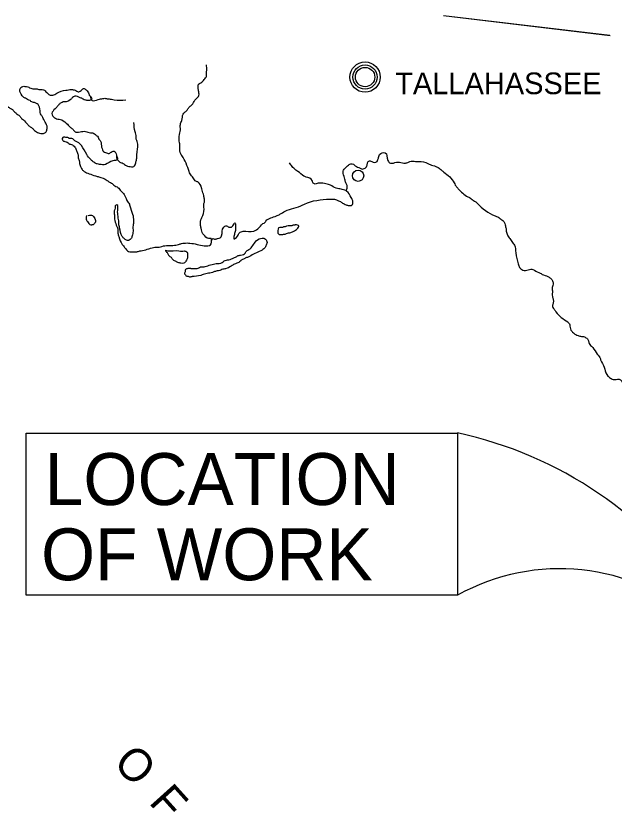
# Model space of a CAD drawing. Extents: x 492225 to 553725, y 1303773 to 1347273.
# Drawn here: x 537404 to 540852, y 1339055 to 1343645 of the extents above; entities that cross this region are included whole.
import ezdxf

# ---------------------------------------------------------------- set-up
doc = ezdxf.new("R2010")
doc.units = 0
for name, color, linetype in [('Level 1', 7, 'Continuous'), ('Level 20', 7, 'Continuous'), ('Level 62', 7, 'Continuous'), ('Level 63', 7, 'Continuous')]:
    doc.layers.add(name, color=color, linetype=linetype)

msp = doc.modelspace()

# ---------------------------------------------------------------- linework, layer by layer
at = {"layer": 'Level 1'}
msp.add_lwpolyline([(539950.039, 1340305.02), (537462.341, 1340305.02), (537462.341, 1341240.247), (539950.039, 1341240.247)], close=True, dxfattribs=at)
for centre, radius, start, end in [((539463.2113, 1338980.6391), 2311.473, 33.7540933, 77.84251), ((540538.5032, 1339245.9527), 1211.5972, 48.8625679, 119.0596401)]:
    msp.add_arc(centre, radius, start, end, dxfattribs=at)
at = {"layer": 'Level 62'}
for radius in [69.8771, 55.9017]:
    msp.add_circle((539416.527, 1343292.5055), radius, dxfattribs=at)
at = {"layer": 'Level 63'}
for p, q in [((540828.4745, 1343531.248), (539868.327, 1343644.788)), ((539336.562, 1342597.5055), (539335.312, 1342598.7555))]:
    msp.add_line(p, q, dxfattribs=at)
for points in [[(540349.062, 1343587.5055), (539867.812, 1343645.0055)], [(540830.312, 1343530.0055), (540349.062, 1343587.5055)]]:
    msp.add_lwpolyline(points, dxfattribs=at)
for centre, radius in [((539416.527, 1343292.5055), 87.3464), ((539376.527, 1342723.7555), 32.5)]:
    msp.add_circle(centre, radius, dxfattribs=at)
for points in [[(536941.562, 1343353.7555), (536991.562, 1343343.7555), (537006.562, 1343336.2555), (537024.062, 1343331.2555), (537042.812, 1343323.7555), (537052.812, 1343321.2555), (537070.312, 1343313.7555), (537082.812, 1343306.2555), (537100.312, 1343293.7555), (537107.812, 1343291.2555), (537122.812, 1343281.2555), (537132.812, 1343276.2555), (537150.312, 1343263.7555), (537171.562, 1343251.2555), (537181.562, 1343243.7555), (537186.562, 1343238.7555), (537201.562, 1343231.2555), (537214.062, 1343221.2555), (537229.062, 1343213.7555), (537249.062, 1343198.7555), (537261.562, 1343191.2555), (537269.062, 1343183.7555), (537300.312, 1343166.2555), (537360.312, 1343118.7555), (537377.812, 1343108.7555), (537387.812, 1343101.2555), (537392.812, 1343093.7555), (537402.812, 1343086.2555), (537407.812, 1343081.2555), (537424.062, 1343068.7555), (537436.562, 1343053.7555), (537446.562, 1343046.2555), (537471.562, 1343018.7555), (537486.562, 1343006.2555), (537494.062, 1343001.2555), (537506.562, 1342988.7555), (537527.812, 1342973.7555), (537540.312, 1342968.7555), (537555.312, 1342966.2555), (537570.312, 1342971.2555), (537577.812, 1342976.2555), (537582.812, 1342996.2555), (537582.812, 1343008.7555), (537576.562, 1343026.2555), (537569.062, 1343040.0055), (537564.062, 1343047.5055), (537559.062, 1343060.0055), (537549.062, 1343075.0055), (537544.062, 1343087.5055), (537536.562, 1343127.5055), (537510.312, 1343145.0055), (537490.312, 1343152.5055), (537485.312, 1343157.5055), (537470.312, 1343162.5055), (537460.312, 1343170.0055), (537452.812, 1343172.5055), (537440.312, 1343185.0055), (537425.312, 1343217.5055), (537432.812, 1343232.5055), (537442.812, 1343238.7555), (537455.312, 1343238.7555), (537472.812, 1343236.2555), (537482.812, 1343231.2555), (537507.812, 1343223.7555), (537525.312, 1343223.7555), (537535.312, 1343221.2555), (537555.312, 1343221.2555), (537567.812, 1343216.2555), (537585.312, 1343198.7555), (537601.562, 1343188.7555), (537616.562, 1343188.7555), (537639.062, 1343198.7555), (537691.562, 1343217.5055), (537699.062, 1343217.5055), (537714.062, 1343220.0055), (537729.062, 1343220.0055), (537749.062, 1343215.0055), (537761.562, 1343207.5055), (537779.062, 1343215.0055), (537794.062, 1343226.2555), (537809.062, 1343218.7555), (537824.062, 1343195.0055), (537826.562, 1343187.5055), (537831.562, 1343182.5055)], [(538531.562, 1342348.7555), (538529.062, 1342361.2555), (538514.062, 1342361.2555), (538486.562, 1342383.7555), (538481.562, 1342388.7555), (538471.562, 1342421.2555), (538467.812, 1342441.2555), (538472.812, 1342477.5055), (538480.312, 1342495.0055), (538487.812, 1342542.5055), (538487.812, 1342563.7555), (538490.312, 1342571.2555), (538490.312, 1342588.7555), (538486.562, 1342608.7555), (538476.562, 1342641.2555), (538474.062, 1342653.7555), (538451.562, 1342687.5055), (538436.562, 1342695.0055), (538429.062, 1342705.0055), (538421.562, 1342717.5055), (538416.562, 1342722.5055), (538407.812, 1342735.0055), (538402.812, 1342747.5055), (538360.312, 1342840.0055), (538354.062, 1342850.0055), (538349.062, 1342886.2555), (538349.062, 1342901.2555), (538346.562, 1342913.7555), (538346.562, 1342961.2555), (538351.562, 1342997.5055), (538350.312, 1343007.5055), (538355.312, 1343030.0055), (538360.312, 1343042.5055), (538367.812, 1343078.7555), (538375.312, 1343088.7555), (538390.312, 1343101.2555), (538395.312, 1343108.7555), (538407.812, 1343123.7555), (538422.812, 1343138.7555), (538440.312, 1343165.0055), (538455.312, 1343180.0055), (538457.812, 1343207.5055), (538455.312, 1343217.5055), (538454.062, 1343235.0055), (538456.562, 1343251.2555), (538469.062, 1343258.7555), (538489.062, 1343278.7555), (538501.562, 1343296.2555), (538501.562, 1343313.7555), (538504.062, 1343332.5055), (538504.062, 1343347.5055), (538501.562, 1343362.5055)], [(537831.562, 1343182.5055), (537840.312, 1343162.5055), (537822.812, 1343157.5055), (537804.062, 1343160.0055), (537791.562, 1343165.0055), (537784.062, 1343170.0055), (537774.062, 1343172.5055), (537759.062, 1343180.0055), (537744.062, 1343182.5055), (537726.562, 1343170.0055), (537721.562, 1343165.0055), (537709.062, 1343156.2555), (537699.062, 1343151.2555), (537676.562, 1343148.7555), (537664.062, 1343143.7555), (537651.562, 1343133.7555), (537639.062, 1343118.7555), (537629.062, 1343108.7555), (537611.562, 1343082.5055), (537616.562, 1343067.5055), (537637.812, 1343052.5055), (537667.812, 1343045.0055), (537700.312, 1343020.0055), (537717.812, 1343002.5055), (537732.812, 1342990.0055), (537745.312, 1342977.5055), (537765.312, 1342975.0055), (537796.562, 1342980.0055), (537811.562, 1342977.5055), (537826.562, 1342972.5055), (537841.562, 1342971.2555), (537861.562, 1342961.2555), (537866.562, 1342956.2555), (537874.062, 1342951.2555), (537879.062, 1342940.0055), (537891.562, 1342922.5055), (537897.812, 1342887.5055), (537902.812, 1342872.5055), (537907.812, 1342862.5055), (537920.312, 1342857.5055), (537940.312, 1342852.5055), (537957.812, 1342862.5055), (537970.312, 1342865.0055), (537982.812, 1342842.5055)], [(537831.562, 1343182.5055), (537842.812, 1343157.5055), (537877.812, 1343162.5055), (537905.312, 1343168.7555), (537925.312, 1343168.7555), (537932.812, 1343166.2555), (537940.312, 1343166.2555), (537970.312, 1343161.2555), (538037.812, 1343161.2555)], [(537982.812, 1342842.5055), (537987.812, 1342817.5055), (538002.812, 1342802.5055), (538021.562, 1342795.0055), (538039.062, 1342782.5055), (538054.062, 1342777.5055), (538069.062, 1342775.0055), (538084.062, 1342777.5055), (538094.062, 1342797.5055), (538099.062, 1342818.7555), (538101.562, 1342841.2555), (538101.562, 1342851.2555), (538102.812, 1342861.2555), (538102.812, 1342920.0055), (538097.812, 1342935.0055), (538097.812, 1342950.0055), (538095.312, 1342962.5055), (538090.312, 1342977.5055), (538084.062, 1343030.0055)], [(537982.812, 1342842.5055), (537987.812, 1342815.0055), (537962.812, 1342810.0055), (537920.312, 1342788.7555), (537885.312, 1342788.7555), (537872.812, 1342791.2555), (537857.812, 1342798.7555), (537840.312, 1342811.2555), (537835.312, 1342816.2555), (537811.562, 1342846.2555), (537781.562, 1342897.5055), (537766.562, 1342912.5055), (537759.062, 1342917.5055), (537744.062, 1342925.0055), (537726.562, 1342937.5055), (537710.312, 1342938.7555), (537702.812, 1342943.7555), (537695.312, 1342943.7555), (537677.812, 1342946.2555), (537670.312, 1342938.7555), (537677.812, 1342923.7555), (537686.562, 1342921.2555), (537699.062, 1342916.2555), (537709.062, 1342908.7555), (537729.062, 1342901.2555), (537746.562, 1342883.7555), (537751.562, 1342873.7555), (537759.062, 1342853.7555), (537761.562, 1342843.7555), (537764.062, 1342821.2555), (537767.812, 1342811.2555), (537770.312, 1342793.7555), (537777.812, 1342772.5055), (537785.312, 1342760.0055), (537797.812, 1342747.5055), (537825.312, 1342735.0055), (537862.812, 1342722.5055), (537881.562, 1342717.5055), (537929.062, 1342696.2555), (537944.062, 1342686.2555), (537954.062, 1342681.2555), (537974.062, 1342666.2555), (537986.562, 1342658.7555), (537996.562, 1342651.2555), (538004.062, 1342641.2555), (538020.312, 1342625.0055), (538027.812, 1342615.0055), (538050.312, 1342570.0055), (538057.812, 1342560.0055), (538060.312, 1342550.0055), (538076.562, 1342502.5055), (538081.562, 1342463.7555), (538081.562, 1342448.7555), (538079.062, 1342436.2555), (538079.062, 1342403.7555), (538074.062, 1342376.2555), (538066.562, 1342360.0055), (538046.562, 1342350.0055), (538029.062, 1342360.0055), (538016.562, 1342372.5055), (538001.562, 1342423.7555), (537996.562, 1342446.2555), (537996.562, 1342463.7555), (537992.812, 1342478.7555), (537992.812, 1342491.2555), (537990.312, 1342506.2555), (537990.312, 1342523.7555), (537985.312, 1342555.0055), (537977.812, 1342552.5055), (537975.312, 1342536.2555), (537970.312, 1342521.2555), (537970.312, 1342503.7555), (537972.812, 1342483.7555), (537972.812, 1342473.7555), (537991.562, 1342405.0055), (537991.562, 1342392.5055), (537996.562, 1342372.5055), (538016.562, 1342327.5055), (538030.312, 1342310.0055), (538052.812, 1342287.5055), (538070.312, 1342285.0055), (538100.312, 1342285.0055), (538117.812, 1342290.0055), (538132.812, 1342292.5055), (538170.312, 1342302.5055), (538180.312, 1342306.2555), (538212.812, 1342311.2555), (538230.312, 1342311.2555), (538245.312, 1342316.2555), (538280.312, 1342321.2555), (538309.062, 1342321.2555)], [(539307.812, 1342638.7555), (539312.812, 1342652.5055), (539312.812, 1342667.5055), (539305.312, 1342682.5055), (539300.312, 1342703.7555), (539290.312, 1342736.2555), (539290.312, 1342751.2555), (539302.812, 1342768.7555), (539307.812, 1342773.7555), (539325.312, 1342787.5055), (539342.812, 1342792.5055), (539355.312, 1342785.0055), (539360.312, 1342780.0055), (539387.812, 1342767.5055), (539395.312, 1342762.5055), (539405.312, 1342762.5055), (539417.812, 1342767.5055), (539427.812, 1342785.0055), (539432.812, 1342802.5055), (539437.812, 1342807.5055), (539445.312, 1342810.0055), (539455.312, 1342805.0055), (539470.312, 1342800.0055), (539485.312, 1342806.2555), (539490.312, 1342816.2555), (539495.312, 1342833.7555), (539500.312, 1342846.2555), (539532.812, 1342856.2555), (539547.812, 1342811.2555), (539562.812, 1342796.2555), (539597.812, 1342801.2555), (539614.062, 1342801.2555), (539649.062, 1342796.2555), (539666.562, 1342802.5055), (539699.062, 1342807.5055), (539716.562, 1342805.0055), (539726.562, 1342805.0055), (539779.062, 1342795.0055), (539791.562, 1342787.5055), (539824.062, 1342777.5055), (539842.812, 1342767.5055), (539852.812, 1342760.0055), (539857.812, 1342755.0055), (539870.312, 1342745.0055), (539930.312, 1342682.5055), (539936.562, 1342670.0055), (539941.562, 1342662.5055), (539954.062, 1342647.5055), (540009.062, 1342602.5055), (540019.062, 1342597.5055), (540037.812, 1342582.5055), (540055.312, 1342572.5055), (540062.812, 1342565.0055), (540166.562, 1342492.5055), (540194.062, 1342477.5055), (540199.062, 1342472.5055), (540211.562, 1342465.0055), (540219.062, 1342455.0055), (540224.062, 1342440.0055), (540229.062, 1342418.7555), (540231.562, 1342398.7555), (540240.312, 1342376.2555), (540255.312, 1342356.2555), (540262.812, 1342343.7555), (540277.812, 1342323.7555), (540285.312, 1342278.7555), (540299.062, 1342215.0055), (540306.562, 1342195.0055), (540326.562, 1342180.0055), (540341.562, 1342177.5055), (540371.562, 1342185.0055), (540384.062, 1342182.5055), (540417.812, 1342165.0055), (540425.312, 1342162.5055), (540437.812, 1342155.0055), (540470.312, 1342142.5055), (540485.312, 1342132.5055), (540497.812, 1342117.5055), (540500.312, 1342097.5055), (540495.312, 1342072.5055), (540496.562, 1342060.0055), (540496.562, 1342027.5055), (540499.062, 1342018.7555), (540499.062, 1341981.2555), (540496.562, 1341973.7555), (540506.562, 1341953.7555), (540516.562, 1341938.7555), (540547.812, 1341906.2555), (540585.312, 1341881.2555)], [(539336.562, 1342597.5055), (539310.312, 1342635.0055), (539300.312, 1342640.0055), (539285.312, 1342645.0055), (539257.812, 1342650.0055), (539225.312, 1342665.0055), (539217.812, 1342670.0055), (539205.312, 1342672.5055), (539190.312, 1342677.5055), (539172.812, 1342680.0055), (539145.312, 1342680.0055), (539124.062, 1342676.2555), (539114.062, 1342688.7555), (539111.562, 1342696.2555), (539076.562, 1342716.2555), (539064.062, 1342721.2555), (539029.062, 1342748.7555), (539016.562, 1342756.2555), (539005.312, 1342766.2555), (538995.312, 1342777.5055), (538980.312, 1342797.5055)], [(538531.562, 1342348.7555), (538539.062, 1342361.2555), (538549.062, 1342358.7555), (538566.562, 1342361.2555), (538581.562, 1342366.2555), (538589.062, 1342377.5055), (538601.562, 1342427.5055), (538614.062, 1342435.0055), (538631.562, 1342427.5055), (538646.562, 1342427.5055), (538661.562, 1342446.2555), (538666.562, 1342451.2555), (538669.062, 1342433.7555), (538669.062, 1342407.5055), (538662.812, 1342385.0055), (538660.312, 1342372.5055), (538660.312, 1342360.0055), (538680.312, 1342375.0055), (538692.812, 1342395.0055), (538712.812, 1342403.7555), (538775.312, 1342403.7555), (538790.312, 1342411.2555), (538820.312, 1342441.2555), (538827.812, 1342447.5055), (538840.312, 1342455.0055), (538845.312, 1342462.5055), (538872.812, 1342480.0055), (538905.312, 1342492.5055), (538925.312, 1342501.2555), (538955.312, 1342518.7555), (539057.812, 1342555.0055), (539067.812, 1342560.0055), (539212.812, 1342588.7555), (539232.812, 1342588.7555), (539259.062, 1342581.2555), (539279.062, 1342571.2555), (539286.562, 1342566.2555), (539306.562, 1342556.2555), (539324.062, 1342551.2555), (539341.562, 1342555.0055), (539346.562, 1342572.5055), (539336.562, 1342597.5055)], [(537812.812, 1342493.7555), (537809.062, 1342487.5055), (537807.812, 1342480.0055), (537810.312, 1342467.5055), (537816.562, 1342460.0055), (537824.062, 1342447.5055), (537830.312, 1342442.5055), (537841.562, 1342441.2555)], [(537820.312, 1342493.7555), (537845.312, 1342493.7555), (537850.312, 1342488.7555), (537857.812, 1342476.2555), (537861.562, 1342456.2555), (537856.562, 1342448.7555), (537849.062, 1342441.2555), (537841.562, 1342441.2555)], [(538916.562, 1342425.0055), (538914.062, 1342407.5055), (538914.062, 1342392.5055), (538921.562, 1342385.0055), (538936.562, 1342385.0055), (538956.562, 1342387.5055), (538969.062, 1342392.5055), (538982.812, 1342395.0055), (539002.812, 1342402.5055), (539015.312, 1342410.0055), (539032.812, 1342426.2555), (539034.062, 1342433.7555), (539014.062, 1342441.2555)], [(538916.562, 1342423.7555), (538926.562, 1342426.2555), (538935.312, 1342426.2555), (538941.562, 1342427.5055), (538949.062, 1342430.0055), (538957.812, 1342431.2555), (538974.062, 1342436.2555), (538981.562, 1342436.2555), (538987.812, 1342437.5055), (538996.562, 1342437.5055), (539002.812, 1342440.0055), (539014.062, 1342441.2555)], [(538309.062, 1342321.2555), (538341.562, 1342327.5055), (538359.062, 1342332.5055), (538374.062, 1342335.0055), (538406.562, 1342335.0055), (538489.062, 1342320.0055), (538501.562, 1342318.7555), (538519.062, 1342321.2555), (538529.062, 1342331.2555), (538531.562, 1342348.7555)], [(538411.562, 1342188.7555), (538441.562, 1342188.7555), (538454.062, 1342191.2555), (538471.562, 1342198.7555), (538489.062, 1342198.7555), (538501.562, 1342201.2555), (538534.062, 1342212.5055), (538566.562, 1342217.5055), (538599.062, 1342227.5055), (538604.062, 1342232.5055), (538631.562, 1342238.7555), (538646.562, 1342243.7555), (538656.562, 1342248.7555), (538664.062, 1342251.2555), (538681.562, 1342261.2555), (538699.062, 1342266.2555), (538726.562, 1342278.7555), (538729.062, 1342285.0055), (538746.562, 1342297.5055), (538789.062, 1342347.5055), (538824.062, 1342363.7555), (538841.562, 1342358.7555), (538851.562, 1342338.7555), (538849.062, 1342328.7555), (538840.312, 1342310.0055), (538822.812, 1342295.0055), (538757.812, 1342262.5055), (538742.812, 1342253.7555), (538725.312, 1342248.7555), (538720.312, 1342243.7555), (538710.312, 1342241.2555), (538697.812, 1342231.2555), (538677.812, 1342218.7555), (538662.812, 1342213.7555), (538645.312, 1342202.5055), (538612.812, 1342187.5055), (538591.562, 1342182.5055), (538579.062, 1342177.5055), (538564.062, 1342175.0055), (538544.062, 1342168.7555), (538514.062, 1342161.2555), (538499.062, 1342158.7555), (538469.062, 1342148.7555), (538419.062, 1342142.5055)], [(538265.312, 1342293.7555), (538277.812, 1342291.2555), (538342.812, 1342291.2555), (538360.312, 1342288.7555), (538372.812, 1342290.0055), (538390.312, 1342282.5055), (538392.812, 1342258.7555), (538390.312, 1342243.7555), (538382.812, 1342231.2555), (538371.562, 1342218.7555), (538355.312, 1342218.7555), (538337.812, 1342223.7555), (538322.812, 1342231.2555), (538307.812, 1342241.2555), (538302.812, 1342248.7555), (538290.312, 1342258.7555)], [(538265.312, 1342293.7555), (538269.062, 1342286.2555), (538275.312, 1342280.0055), (538282.812, 1342265.0055), (538290.312, 1342258.7555)], [(538411.562, 1342188.7555), (538395.312, 1342188.7555), (538387.812, 1342186.2555), (538381.562, 1342182.5055), (538379.062, 1342175.0055), (538377.812, 1342165.0055), (538375.312, 1342157.5055), (538381.562, 1342152.5055), (538384.062, 1342146.2555), (538394.062, 1342145.0055), (538400.312, 1342142.5055), (538419.062, 1342142.5055)], [(540585.312, 1341881.2555), (540590.312, 1341873.7555), (540595.312, 1341868.7555), (540597.812, 1341856.2555), (540607.812, 1341827.5055), (540612.812, 1341822.5055), (540631.562, 1341807.5055), (540644.062, 1341802.5055), (540664.062, 1341797.5055), (540676.562, 1341796.2555), (540694.062, 1341786.2555), (540701.562, 1341778.7555), (540706.562, 1341762.5055), (540721.562, 1341740.0055), (540729.062, 1341732.5055), (540755.312, 1341695.0055), (540772.812, 1341667.5055), (540775.312, 1341657.5055), (540780.312, 1341650.0055), (540816.562, 1341568.7555), (540821.562, 1341563.7555), (540841.562, 1341551.2555), (540854.062, 1341548.7555), (540889.062, 1341547.5055), (540901.562, 1341526.2555), (540906.562, 1341508.7555), (540912.812, 1341498.7555), (540917.812, 1341473.7555), (540932.812, 1341433.7555), (540940.312, 1341421.2555), (540952.812, 1341406.2555), (540965.312, 1341401.2555), (540980.312, 1341398.7555), (541012.812, 1341413.7555), (541031.562, 1341413.7555), (541069.062, 1341408.7555), (541111.562, 1341396.2555), (541116.562, 1341391.2555), (541126.562, 1341390.0055), (541159.062, 1341390.0055), (541164.062, 1341395.0055), (541174.062, 1341395.0055), (541194.062, 1341400.0055), (541206.562, 1341400.0055), (541224.062, 1341405.0055)]]:
    msp.add_spline(points, degree=3, dxfattribs=at)

# ---------------------------------------------------------------- texts
at = {"layer": 'Level 1'}
for s, p in [('LOCATION', (537570.139, 1340824.987)), (' OF WORK', (537437.711, 1340391.24))]:
    msp.add_text(s, height=299.25, dxfattribs=at).set_placement(p)
at = {"layer": 'Level 20'}
for s, rotation, p in [('O', 314.8228269, (537957.6745, 1339329.348)), ('F', 311.934241, (538165.1745, 1339108.098))]:
    msp.add_text(s, height=187.4992, rotation=rotation, dxfattribs=at).set_placement(p)
at = {"layer": 'Level 62'}
msp.add_text('TALLAHASSEE', height=125.0025, dxfattribs=at).set_placement((539590.312, 1343193.7555))

doc.saveas('drawing.dxf')
